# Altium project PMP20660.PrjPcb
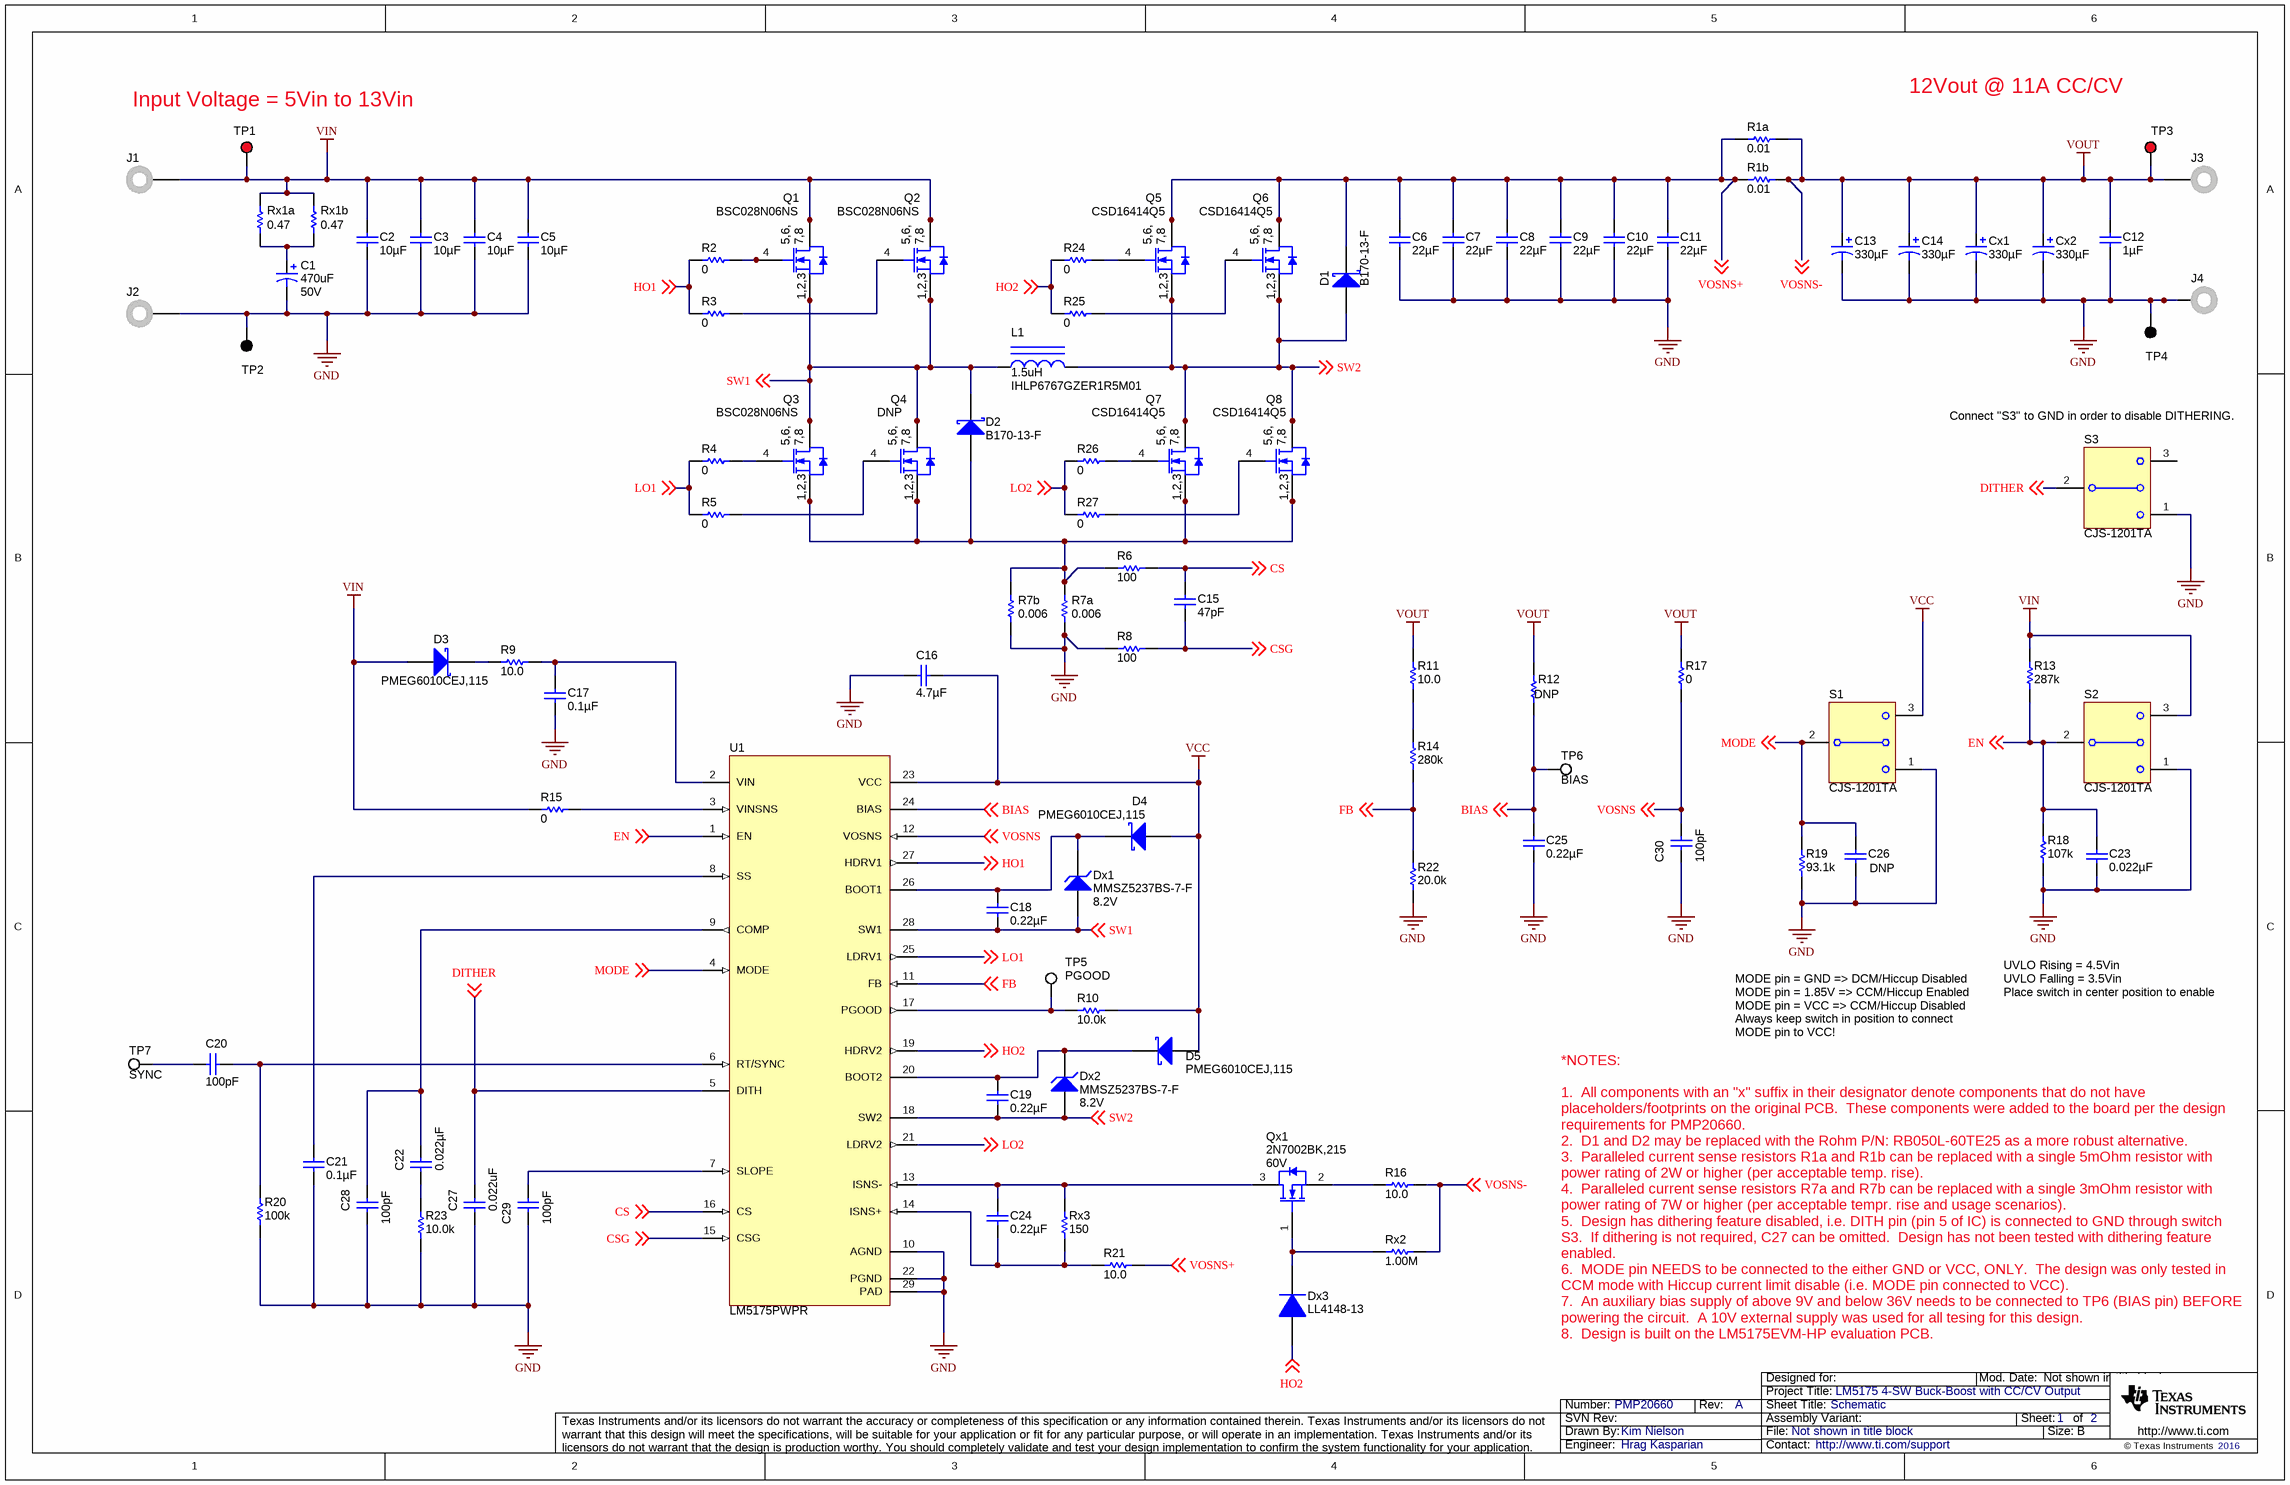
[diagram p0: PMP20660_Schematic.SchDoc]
CopyrightYear: 2016; PRJ_Engineer: Hrag Kasparian; PRJ_Number: PMP20660; PRJ_Title: LM5175 4-SW Buck-Boost with CC/CV Output; SCH_Rev: A; TechSupport: http://www.ti.com/support; TID: PMP20660
2 sheets, 113 parts. Net scope: global (net labels, ports and power ports of the same name join across sheets).
Board file: PMP20660_PCB.PcbDoc
Sheets:
  PMP20660_Schematic.SchDoc
  PMP20660_Hardware.SchDoc

## Sheet PMP20660_Schematic.SchDoc: Schematic
size 431 x 279 mm; Date: Not shown in title block; ApprovedBy: Not shown in title block; CheckedBy: Not shown in title block; Author: Not shown in title block; CompanyName: Not shown in title block; DrawnBy: Kim Nielson; Engineer: Neil Gutierrez; Organization: Not shown in title block; Address1: Not shown in title block; Address2: Not shown in title block; Address3: Not shown in title block; Address4: Not shown in title block; DocumentNumber: 1; Revision: Use project parameter SCH_Rev; SheetNumber: 1; SheetTotal: 2; PageSetup: Record=PageOptions¦CenterHorizontal=True¦CenterVertical=True¦PrintScale=0.62¦XCorrection=1.00¦YCorrection=1.00¦PrintKind=0¦BorderSize=5000000¦LeftOffset=0¦BottomOffset=0¦Orientation=2¦PaperLength=1000¦PaperWidth=1000¦Scale=100¦PaperSource=15¦PrintQuality=600¦MediaType=1¦DitherType=10¦PaperKind=Letter¦PrintScaleMode=1

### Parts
C1  value 470uF  Value1: 50V  [TBD]  (hidden comment: EMVH500ADA471MMH0S)
C2  ValueDisplayed: 10µF  [1210]  (hidden comment: GRM32ER71H106KA12L)
C3  ValueDisplayed: 10µF  [1210]  (hidden comment: GRM32ER71H106KA12L)
C4  ValueDisplayed: 10µF  [1210]  (hidden comment: GRM32ER71H106KA12L)
C5  ValueDisplayed: 10µF  [1210]  (hidden comment: GRM32ER71H106KA12L)
C6  ValueDisplayed: 22µF  [1210]  (hidden comment: GRM32ER71C226ME18L)
C7  ValueDisplayed: 22µF  [1210]  (hidden comment: GRM32ER71C226ME18L)
C8  ValueDisplayed: 22µF  [1210]  (hidden comment: GRM32ER71C226ME18L)
C9  ValueDisplayed: 22µF  [1210]  (hidden comment: GRM32ER71C226ME18L)
C10  ValueDisplayed: 22µF  [1210]  (hidden comment: GRM32ER71C226ME18L)
C11  ValueDisplayed: 22µF  [1210]  (hidden comment: GRM32ER71C226ME18L)
C12  ValueDisplayed: 1µF  [0805_HV]  (hidden comment: GRM219R71E105KA88D)
C13  ValueDisplayed: 330µF  [SM_RADIAL_10AMM]  (hidden comment: 16SVP330M)
C14  ValueDisplayed: 330µF  [SM_RADIAL_10AMM]  (hidden comment: 16SVP330M)
C15  ValueDisplayed: 47pF  [0603L]  (hidden comment: GRM1885C1H470JA01D)
C16  ValueDisplayed: 4.7µF  [0805_HV]  (hidden comment: GRM21BR71C475KA73L)
C17  ValueDisplayed: 0.1µF  [0603L]  (hidden comment: GRM188R72A104KA35D)
C18  ValueDisplayed: 0.22µF  [0603L]  (hidden comment: GRM188R71E224KA88D)
C19  ValueDisplayed: 0.22µF  [0603L]  (hidden comment: GRM188R71E224KA88D)
C20  ValueDisplayed: 100pF  [0603L]  (hidden comment: GRM1885C2A101JA01D)
C21  ValueDisplayed: 0.1µF  [0603L]  (hidden comment: GRM188R72A104KA35D)
C22  ValueDisplayed: 0.022µF  [0603L]  (hidden comment: C0603C223K5RACTU)
C23  ValueDisplayed: 0.022µF  [0603]  (hidden comment: GRM188R71H223KA01D)
C24  ValueDisplayed: 0.22µF  [0603]  (hidden comment: GRM188R71E224KA88D)
C25  ValueDisplayed: 0.22µF  [0603]  (hidden comment: GRM188R71E224KA88D)
C26  DNP  [0603L]
C27  0.022uF  [0603L]
C28  ValueDisplayed: 100pF  [0603L]  (hidden comment: GRM1885C2A101JA01D)
C29  ValueDisplayed: 100pF  [0603L]  (hidden comment: GRM1885C2A101JA01D)
C30  ValueDisplayed: 100pF  [0603L]  (hidden comment: GRM1885C2A101JA01D)
Cx1  ValueDisplayed: 330µF  [SM_RADIAL_10AMM]  (hidden comment: 16SVP330M)
Cx2  ValueDisplayed: 330µF  [SM_RADIAL_10AMM]  (hidden comment: 16SVP330M)
D1  B170-13-F  [SMA]
D2  B170-13-F  [SMA]
D3  PMEG6010CEJ,115  [SOD-323F]
D4  PMEG6010CEJ,115  [SOD-323F]
D5  PMEG6010CEJ,115  [SOD-323F]
Dx1  MMSZ5237BS-7-F  value 8.2V  [SOD-323]
Dx2  MMSZ5237BS-7-F  value 8.2V  [SOD-323]
Dx3  LL4148-13  [TBD]
J1  108-0740-001  [Johnson_108-0740-001]  (value not drawn)
J2  108-0740-001  [Johnson_108-0740-001]  (value not drawn)
J3  108-0740-001  [Johnson_108-0740-001]  (value not drawn)
J4  108-0740-001  [Johnson_108-0740-001]  (value not drawn)
L1  IHLP6767GZER1R5M01  value 1.5uH
Q1  BSC028N06NS  [PG-TDSON-8]
Q2  BSC028N06NS  [PG-TDSON-8]
Q3  BSC028N06NS  [PG-TDSON-8]
Q4  DNP  [PG-TDSON-8]
Q5  CSD16414Q5  [DQH0008A]
Q6  CSD16414Q5  [DQH0008A]
Q7  CSD16414Q5  [DQH0008A]
Q8  CSD16414Q5  [DQH0008A]
Qx1  2N7002BK,215  value 60V  [SOT-23]
R1a  ValueDisplayed: 0.01  [3008M]  (hidden comment: RL7520WT-R010-F)
R1b  ValueDisplayed: 0.01  [3008M]  (hidden comment: RL7520WT-R010-F)
R2  value 0  [0603L]  (hidden comment: RC0603JR-070RL)
R3  value 0  [0603L]  (hidden comment: RC0603JR-070RL)
R4  value 0  [0603L]  (hidden comment: RC0603JR-070RL)
R5  value 0  [0603L]  (hidden comment: RC0603JR-070RL)
R6  value 100  [0603_HV]  (hidden comment: RC0603FR-07100RL)
R7a  value 0.006  [TBD]  (hidden comment: WSHM28186L000FEA)
R7b  value 0.006  [TBD]  (hidden comment: WSHM28186L000FEA)
R8  value 100  [0603_HV]  (hidden comment: RC0603FR-07100RL)
R9  value 10.0  [0603L]  (hidden comment: RC0603FR-0710RL)
R10  value 10.0k  [0603L]  (hidden comment: RC0603FR-0710KL)
R11  value 10.0  [0603L]  (hidden comment: RC0603FR-0710RL)
R12  DNP  [0603L]
R13  ValueDisplayed: 287k  [0603]  (hidden comment: CRCW0603287KFKEA)
R14  value 280k  [0603L]  (hidden comment: RC0603FR-07280KL)
R15  value 0  [0603L]  (hidden comment: RC0603JR-070RL)
R16  ValueDisplayed: 10.0  [0603]  (hidden comment: CRCW060310R0FKEA)
R17  value 0  [0603L]  (hidden comment: RC0603JR-070RL)
R18  ValueDisplayed: 107k  [0603]  (hidden comment: CRCW0603107KFKEA)
R19  ValueDisplayed: 93.1k  [0603L]  (hidden comment: RC0603FR-0793K1L)
R20  ValueDisplayed: 100k  [0603L]  (hidden comment: RC0603FR-07100KL)
R21  ValueDisplayed: 10.0  [0603]  (hidden comment: CRCW060310R0FKEA)
R22  value 20.0k  [0603L]  (hidden comment: RC0603FR-0720KL)
R23  value 10.0k  [0603L]  (hidden comment: RC0603FR-0710KL)
R24  value 0  [0603L]  (hidden comment: RC0603JR-070RL)
R25  value 0  [0603L]  (hidden comment: RC0603JR-070RL)
R26  value 0  [0603L]  (hidden comment: RC0603JR-070RL)
R27  value 0  [0603L]  (hidden comment: RC0603JR-070RL)
Rx1a  value 0.47  [TBD]  (hidden comment: RL73K3AR47J)
Rx1b  value 0.47  [TBD]  (hidden comment: RL73K3AR47J)
Rx2  ValueDisplayed: 1.00M  [0603]  (hidden comment: CRCW06031M00FKEA)
Rx3  ValueDisplayed: 150  [0603]  (hidden comment: CRCW0603150RFKEA)
S1  CJS-1201TA  [SW_CJS_1201A]
S2  CJS-1201TA  [SW_CJS_1201A]
S3  CJS-1201TA  [SW_CJS_1201A]
TP1  5005  [Keystone5005]  (value not drawn)
TP2  5006  [Keystone5006]  (value not drawn)
TP3  5005  [Keystone5005]  (value not drawn)
TP4  5006  [Keystone5006]  (value not drawn)
TP5  value PGOOD  [Keystone5007]  (hidden comment: 5007)
TP6  BIAS  [Keystone5007]
TP7  SYNC  [Keystone5007]
U1  LM5175PWPR  [PWP0028F_N]

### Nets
GND: C1.2(-) C2.2 C3.2 C4.2 C5.2 C6.2 C7.2 C8.2 C9.2 C10.2 C11.2 C12.2 C13.2(-) C14.2(-) C16.1 C17.2 C21.2 C23.2 C25.2 C26.2 C27.2 C28.2 C29.2 C30.2 Cx1.2(-) Cx2.2(-) J2.1 J4.1 R7a.1 R7b.1 R8.2 R18.1 R19.1 R20.1 R22.1 R23.1 S1.1 S2.1 S3.1 TP2.1 TP4.1 U1.10(AGND) U1.22(PGND) U1.29(PAD)
VCC: C16.2 D4.2(A) D5.2(A) R10.2 S1.3 U1.23(VCC)
VIN: C2.1 C3.1 C4.1 C5.1 D3.2(A) J1.1 Q1.5(D) Q1.6(D) Q1.7(D) Q1.8(D) Q1.9(D) Q2.5(D) Q2.6(D) Q2.7(D) Q2.8(D) Q2.9(D) R13.2 R15.2 Rx1a.2 Rx1b.2 S2.3 TP1.1
VOUT: C12.1 C13.1(+) C14.1(+) Cx1.1(+) Cx2.1(+) J3.1 R1a.2 R1b.2 R11.1 R12.1 R16.2 R17.1 Rx2.2 TP3.1 ; off-sheet VOSNS-  [also labelled VOSNS-]
BIAS: C25.1 R12.2 TP6.1 U1.24(BIAS) ; off-sheet BIAS
CS: C15.1 R6.1 U1.16(CS) ; off-sheet CS
CSG: C15.2 R8.1 U1.15(CSG) ; off-sheet CSG
DITHER: C27.1 S3.2(COM) U1.5(DITH) ; off-sheet DITHER
EN: C23.1 R13.1 R18.2 S2.2(COM) U1.1(EN) ; off-sheet EN
FB: R14.1 R22.2 U1.11(FB) ; off-sheet FB
HO1: R2.2 R3.2 U1.27(HDRV1) ; off-sheet HO1
HO2: Dx3.2(A) R24.2 R25.2 U1.19(HDRV2) ; off-sheet HO2
LO1: R4.2 R5.2 U1.25(LDRV1) ; off-sheet LO1
LO2: R26.2 R27.2 U1.21(LDRV2) ; off-sheet LO2
MODE: C26.1 R19.2 S1.2(COM) U1.4(MODE) ; off-sheet MODE
SW1: C18.1 D2.1(K) Dx1.2(A) L1.1 Q1.1(S) Q1.2(S) Q1.3(S) Q2.1(S) Q2.2(S) Q2.3(S) Q3.5(D) Q3.6(D) Q3.7(D) Q3.8(D) Q3.9(D) Q4.5(D) Q4.6(D) Q4.7(D) Q4.8(D) Q4.9(D) U1.28(SW1) ; off-sheet SW1
SW2: C19.2 D1.2(A) Dx2.2(A) L1.2 Q5.1(S) Q5.2(S) Q5.3(S) Q6.1(S) Q6.2(S) Q6.3(S) Q7.5(D) Q7.6(D) Q7.7(D) Q7.8(D) Q7.9(D) Q8.5(D) Q8.6(D) Q8.7(D) Q8.8(D) Q8.9(D) U1.18(SW2) ; off-sheet SW2
VOSNS: C30.1 R17.2 U1.12(VOSNS) ; off-sheet VOSNS
VOSNS+: C6.1 C7.1 C8.1 C9.1 C10.1 C11.1 D1.1(K) Q5.5(D) Q5.6(D) Q5.7(D) Q5.8(D) Q5.9(D) Q6.5(D) Q6.6(D) Q6.7(D) Q6.8(D) Q6.9(D) R1a.1 R1b.1 R21.2 ; off-sheet VOSNS+
NetC1_1: C1.1(+) Rx1a.1 Rx1b.1
NetC17_1: C17.1 R9.1 U1.2(VIN)
NetC18_2: C18.2 D4.1(K) Dx1.1(K) U1.26(BOOT1)
NetC19_1: C19.1 D5.1(K) Dx2.1(K) U1.20(BOOT2)
NetC20_1: C20.1 TP7.1
NetC20_2: C20.2 R20.2 U1.6(RT/SYNC)
NetC21_1: C21.1 U1.8(SS)
NetC22_1: C22.1 C28.1 U1.9(COMP)
NetC22_2: C22.2 R23.2
NetC24_1: C24.1 Qx1.3(D) Rx3.2 U1.13(ISNS-)
NetC24_2: C24.2 R21.1 Rx3.1 U1.14(ISNS+)
NetC29_1: C29.1 U1.7(SLOPE)
NetD2_2: D2.2(A) Q3.1(S) Q3.2(S) Q3.3(S) Q4.1(S) Q4.2(S) Q4.3(S) Q7.1(S) Q7.2(S) Q7.3(S) Q8.1(S) Q8.2(S) Q8.3(S) R6.2 R7a.2 R7b.2
NetD3_1: D3.1(K) R9.2
NetDx3_1: Dx3.1(K) Qx1.1(G) Rx2.1
NetQ1_4: Q1.4(G) R2.1
NetQ2_4: Q2.4(G) R3.1
NetQ3_4: Q3.4(G) R4.1
NetQ4_4: Q4.4(G) R5.1
NetQ5_4: Q5.4(G) R24.1
NetQ6_4: Q6.4(G) R25.1
NetQ7_4: Q7.4(G) R26.1
NetQ8_4: Q8.4(G) R27.1
NetQx1_2: Qx1.2(S) R16.1
NetR10_1: R10.1 TP5.1 U1.17(PGOOD)
NetR11_2: R11.2 R14.2
NetR15_1: R15.1 U1.3(VINSNS)

Not connected (* = marked no-connect by the designer): S3 3

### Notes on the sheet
- (near TP1) Input Voltage = 5Vin to 13Vin
- 12Vout @ 11A CC/CV
- (near S3) Connect "S3" to GND in order to disable DITHERING.
- MODE pin = GND => DCM/Hiccup Disabled
  MODE pin = 1.85V => CCM/Hiccup Enabled
  MODE pin = VCC => CCM/Hiccup Disabled
  Always keep switch in position to connect MODE pin to VCC!
- UVLO Rising = 4.5Vin
  UVLO Falling = 3.5Vin
  Place switch in center position to enable UVLO function.
- *NOTES:
  1.  All components with an "x" suffix in their designator denote components that do not have placeholders/footprints on the original PCB.  These components were added to the board per the design requirements for PMP20660.
  2.  D1 and D2 may be replaced with the Rohm P/N: RB050L-60TE25 as a more robust alternative.
  3.  Paralleled current sense resistors R1a and R1b can be replaced with a single 5mOhm resistor with power rating of 2W or higher (per acceptable temp. rise).
  4.  Paralleled current sense resistors R7a and R7b can be replaced with a single 3mOhm resistor with power rating of 7W or higher (per acceptable tempr. rise and usage scenarios).
  5.  Design has dithering feature disabled, i.e. DITH pin (pin 5 of IC) is connected to GND through switch S3.  If dithering is not required, C27 can be omitted.  Design has not been tested with dithering feature enabled.
  6.  MODE pin NEEDS to be connected to the either GND or VCC, ONLY.  The design was only tested in CCM mode with Hiccup current limit disable (i.e. MODE pin connected to VCC).
  7.  An auxiliary bias supply of above 9V and below 36V needs to be connected to TP6 (BIAS pin) BEFORE powering the circuit.  A 10V external supply was used for all tesing for this design.
  8.  Design is built on the LM5175EVM-HP evaluation PCB.

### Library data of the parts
C1 = Capacitor_Polarized: CAP, Al Electrolytic, 470uF, 50V, +/-%, 0.15Ohm ESR, 125C, SMT; Manufacturer: Nippon Chemi-Con; Polarized: Y; U/M: EA
C2-C5 = GRM32ER71H106KA12L: CAP, CERM, 10 µF, 50 V, +/- 10%, X7R, 1210; Manufacturer: MuRata; CompType: Capacitor; Value: 10uF; U/M: EA; Tolerance_%: 10; VDC_V: 50; Polarized: N; Cap_F: 0.00001; Value1: Unknown; Value2: 50V; TaMin_C: -55; TaMax_C: 125
C6-C11 = GRM32ER71C226ME18L: CAP, CERM, 22 µF, 16 V, +/- 20%, X7R, 1210; Manufacturer: MuRata; CompType: Capacitor; Value: 22uF; U/M: EA; Tolerance_%: 20; VDC_V: 16; Polarized: N; Cap_F: 0.000022; ESR_ohm: 0.003; Value1: 0.003 ohm; Value2: 16V; IRMS_A: 3.2; TaMin_C: -55; TaMax_C: 125
C12 = GRM219R71E105KA88D: CAP, CERM, 1 µF, 25 V, +/- 10%, X7R, 0805; Manufacturer: MuRata; Polarized: N; CompType: Capacitor; Value: 1uF; U/M: EA; Cap_F: 0.000001; Tolerance_%: 10; Value1: Unknown; VDC_V: 25; Value2: 25V; TaMin_C: -55; TaMax_C: 125; Cap_Case: 0805
C13 C14 Cx1 Cx2 = 16SVP330M: CAP, OS-CON, 330 µF, 16 V, +/- 20%, 0.016 ohm, 10x10.3 SMD; Manufacturer: Sanyo; CompType: Capacitor; Value: 330uF; U/M: EA; Tolerance_%: 20; VDC_V: 16; ESR_ohm: 0.016; Polarized: Y; Cap_F: 0.00033; Value2: 16V; IRMS_A: 4.72; TaMin_C: -55; TaMax_C: 105; Cap_Case: 10.3x10.3x12.6
C15 C26 = GRM1885C1H470JA01D: CAP, CERM, 47pF, 50V, +/-5%, C0G/NP0, 0603; Manufacturer: MuRata; Polarized: N; CompType: Capacitor; U/M: EA; Cap_F: 0.000000000047; Tolerance_%: 5; Value1: Unknown; VDC_V: 50; TaMin_C: -55; TaMax_C: 125; Cap_Case: 0603
C16 = GRM21BR71C475KA73L: CAP, CERM, 4.7 µF, 16 V, +/- 10%, X7R, 0805; Manufacturer: MuRata; Polarized: N; CompType: Capacitor; Value: 4.7uF; U/M: EA; Cap_F: 0.0000047; Tolerance_%: 10; ESR_ohm: 0.006; Value1: 0.006 ohm; VDC_V: 16; Value2: 16V; TaMin_C: -55; TaMax_C: 125; Cap_Case: 0805
C17 C21 = GRM188R72A104KA35D: CAP, CERM, 0.1uF, 100V, +/-10%, X7R, 0603; Manufacturer: MuRata; Polarized: N; CompType: Capacitor; U/M: EA; Cap_F: 0.0000001; Tolerance_%: 10; Value1: Unknown; VDC_V: 100; TaMin_C: -55; TaMax_C: 125; Cap_Case: 0603
C18 C19 = GRM188R71E224KA88D: CAP, CERM, 0.22 µF, 25 V, +/- 10%, X7R, 0603; Manufacturer: MuRata; Polarized: N; CompType: Capacitor; Value: 0.22uF; U/M: EA; Cap_F: 0.00000022; Tolerance_%: 10; Value1: Unknown; VDC_V: 25; Value2: 25V; TaMin_C: -55; TaMax_C: 125; Cap_Case: 0603
C20 C28-C30 = GRM1885C2A101JA01D: CAP, CERM, 100pF, 100V, +/-5%, C0G/NP0, 0603; Manufacturer: MuRata; Polarized: N; CompType: Capacitor; U/M: EA; Cap_F: 0.0000000001; Tolerance_%: 5; Value1: Unknown; VDC_V: 100; TaMin_C: -55; TaMax_C: 125; Cap_Case: 0603
C22 = C0603C223K5RACTU: CAP, CERM, 0.022uF, 50V, +/-10%, X7R, 0603; Manufacturer: Kemet; Polarized: N; CompType: Capacitor; U/M: EA; Cap_F: 0.000000022; Tolerance_%: 10; Value1: Unknown; VDC_V: 50; TaMin_C: -55; TaMax_C: 125; Cap_Case: 0603
C23 = GRM188R71H223KA01D: CAP, CERM, 0.022 µF, 50 V, +/- 10%, X7R, 0603; Manufacturer: MuRata; Polarized: N; CompType: Capacitor; Value: 0.022uF; U/M: EA; Cap_F: 0.000000022; Tolerance_%: 10; Value1: Unknown; VDC_V: 50; Value2: 50V; TaMin_C: -55; TaMax_C: 125; SizeArea_mm2: 1.28; SizeAreaWB_mm2: 4.68; SizeX_mm: 1.6; SizeY_mm: 0.8; SizeZ_mm: 1; AEC Category: Q200
C24 = GRM188R71E224KA88D: CAP, CERM, 0.22 µF, 25 V, +/- 10%, X7R, 0603; Manufacturer: MuRata; Polarized: N; CompType: Capacitor; Value: 0.22uF; U/M: EA; Cap_F: 0.00000022; Tolerance_%: 10; Value1: Unknown; VDC_V: 25; Value2: 25V; TaMin_C: -55; TaMax_C: 125; SizeArea_mm2: 1.28; SizeAreaWB_mm2: 4.68; SizeX_mm: 1.6; SizeY_mm: 0.8; SizeZ_mm: 1; AEC Category: Q200
C25 = GRM188R71E224KA88D: CAP, CERM, 0.22 µF, 25 V, +/- 10%, X7R, 0603; Manufacturer: MuRata; Polarized: N; CompType: Capacitor; Value: 0.22uF; U/M: EA; Cap_F: 0.00000022; Tolerance_%: 10; Value1: Unknown; VDC_V: 25; Value2: 25V; TaMin_C: -55; TaMax_C: 125
C27 = C0603C223K5RACTU: CAP, CERM, 0.022uF, 50V, +/-10%, X7R, 0603; Manufacturer: Kemet; Polarized: N; CompType: Capacitor; ValueDisplayed: 0.022µF; U/M: EA; Cap_F: 0.000000022; Tolerance_%: 10; Value1: Unknown; VDC_V: 50; TaMin_C: -55; TaMax_C: 125; Cap_Case: 0603
D1 D2 = B170-13-F: Diode, Schottky, 70 V, 1 A, SMA; Manufacturer: Diodes Inc.; U/M: EA; Vf_V: 0.79; Value: 70V; Value1: 1A; Value2: 0.79V; Io_A: 1; Vr_V: 70; TJmax_C: 150; RJC_CperW: 25; SizeAreaWB_mm2: 37.3428; SizeArea_mm2: 16.3228; SizeX_mm: 5.59; SizeY_mm: 2.92; SizeZ_mm: 2.87; AEC Category: Q101
D3 = PMEG6010CEJ,115: Diode, Schottky, 60 V, 1 A, SOD-323F; Manufacturer: NXP Semiconductor; U/M: EA; Vf_V: 0.66; Value: 60V; Value1: 1A; Value2: 0.66V; Io_A: 1; Vr_V: 60; TJmax_C: 150
D4 D5 = PMEG6010CEJ,115: Diode, Schottky, 60 V, 1 A, SOD-323F; Manufacturer: NXP Semiconductor; U/M: EA; Vr_V: 60; Value: 60V; Io_A: 1; Vf_V: 0.66; Value1: 1A; Value2: 0.66V; TJmax_C: 150; SizeAreaWB_mm2: 7.875; SizeArea_mm2: 3.125; SizeX_mm: 2.5; SizeY_mm: 1.25; SizeZ_mm: 0.8; AEC Category: Q101
Dx1 Dx2 = MMSZ5237BS-7-F: Diode, Zener, 8.2 V, 200 mW, SOD-323; Manufacturer: Diodes Inc.; SymbolCreator: a0412235; U/M: EA; Power_W: 0.2; Vz_V: 8.2; Value1: 0.2W; RJA_CperW: 350; SizeAreaWB_mm2: 8.695; SizeArea_mm2: 3.645; SizeX_mm: 2.7; SizeY_mm: 1.35; SizeZ_mm: 1; AEC Category: Q101
Dx3 = Diode: Diode, Standard, 75V, 150mA, MINI-MELF; Manufacturer: Diodes Inc.; U/M: EA
J1-J4 = 108-0740-001: Standard Banana Jack, Uninsulated, 15A; Manufacturer: Emerson Network Power; SymbolCreator: a0412235; CompType: Connector; U/M: EA
L1 = Inductor_Iron: Inductor, Molded, Shielded, 1.5uH, 42Arms, 65Asat, 1.88mOhm, SMT; Manufacturer: Vishay Dale; U/M: EA
Q1-Q4 = BSC028N06NS: MOSFET, N-CH, 60 V, 100 A, PG-TDSON-8; Manufacturer: Infineon Technologies; Alternate Manufacturer: None; U/M: EA; ChType: N; Value: 60V; VdsMax_V: 60; Value1: ? ohm; Value2: 37 nC; QgTyp_nC: 37; Vgs_V: 20; IdsMax_A: 100
Q5-Q8 = CSD16414Q5: MOSFET, N-CH, 25 V, 100 A, VSON-CLIP-8; Manufacturer: Texas Instruments; Alternate Manufacturer: None; U/M: EA; ChType: N; Value: 25V; VdsMax_V: 25; Value1: 0.0026 ohm; Rdson45_ohm: 0.0026; Value2: 16.6 nC; QgTyp_nC: 16.6; Vgs_V: 16; IdsMax_A: 100; SizeAreaWB_mm2: 56; SizeArea_mm2: 30; SizeX_mm: 6; SizeY_mm: 5; SizeZ_mm: 1.05; AEC Category: Q101
Qx1 = MOSFET_N_D3G1S2: MOSFET, N-CH, 60V, 350mA, 1.6 Ohm @ 10Vgs, SOT-23; Manufacturer: NXP USA; U/M: EA
R1a R1b = RL7520WT-R010-F: RES, 0.01, 1%, 2 W, 3008; Manufacturer: Susumu Co Ltd; CompType: Resistor; Value: 0.01; Value_Code: R010; Tolerance_%: 1; Power_W: 2; Value2: 2W; TempCo: 350 ppm/C; SizeArea_mm2: 15; SizeAreaWB_mm2: 38; SizeX_mm: 7.5; SizeZ_mm: 0.6; EIA_Code: E96; U/M: EA; AEC Category: Q200
R2-R5 R15 R17 R24-R27 = RC0603JR-070RL: RES, 0 ohm, 5%, 0.1W, 0603; Manufacturer: Yageo America; CompType: Resistor; Value_Code: 0000; Tolerance_%: 5; Power_W: 0.1; VDC_V: 50; TempCo: 200 ppm/C; EIA_Code: E24; U/M: EA
R6 R8 = RC0603FR-07100RL: RES, 100 ohm, 1%, 0.1W, 0603; Manufacturer: Yageo America; CompType: Resistor; Value_Code: 100R; Tolerance_%: 1; Power_W: 0.1; VDC_V: 150; TempCo: 200 ppm/C; EIA_Code: E96; U/M: EA
R7a R7b = Resistor: RES, 0.006 ohm, 1%, 7W, 2818; Manufacturer: Vishay Dale; U/M: EA
R9 R11 = RC0603FR-0710RL: RES, 10.0 ohm, 1%, 0.1W, 0603; Manufacturer: Yageo America; CompType: Resistor; Res_ohm: 10; Value_Code: 10R0; Tolerance_%: 1; Power_W: 0.1; VDC_V: 150; TempCo: 200 ppm/C; EIA_Code: E96; U/M: EA
R10 R23 = RC0603FR-0710KL: RES, 10.0k ohm, 1%, 0.1W, 0603; Manufacturer: Yageo America; CompType: Resistor; Res_ohm: 10000; Value_Code: 10k0; Tolerance_%: 1; Power_W: 0.1; VDC_V: 150; TempCo: 200 ppm/C; EIA_Code: E96; U/M: EA
R12 = RC0603JR-070RL: RES, 0 ohm, 5%, 0.1W, 0603; Manufacturer: Yageo America; CompType: Resistor; Value: 0; Value_Code: 0000; Tolerance_%: 5; Power_W: 0.1; VDC_V: 50; TempCo: 200 ppm/C; EIA_Code: E24; U/M: EA
R13 = CRCW0603287KFKEA: RES, 287 k, 1%, 0.1 W, 0603; Manufacturer: Vishay-Dale; CompType: Resistor; Value: 287k; Res_ohm: 287000; Tolerance_%: 1; Power_W: 0.1; Value2: 0.1W; VDC_V: 75; TempCo: 100 ppm/C; EIA_Code: E96; U/M: EA; SizeArea_mm2: 1.28; SizeX_mm: 1.6; SizeY_mm: 0.8; AEC Category: Q200
R14 = RC0603FR-07280KL: RES, 280k ohm, 1%, 0.1W, 0603; Manufacturer: Yageo America; CompType: Resistor; Res_ohm: 280000; Tolerance_%: 1; Power_W: 0.1; VDC_V: 150; TempCo: 200 ppm/C; EIA_Code: E96; U/M: EA
R16 R21 = CRCW060310R0FKEA: RES, 10.0, 1%, 0.1 W, 0603; Manufacturer: Vishay-Dale; CompType: Resistor; Value: 10.0; Res_ohm: 10; Value_Code: 10R0; Tolerance_%: 1; Power_W: 0.1; Value2: 0.1W; VDC_V: 75; TempCo: 100 ppm/C; EIA_Code: E96; U/M: EA; SizeArea_mm2: 1.28; SizeX_mm: 1.6; SizeY_mm: 0.8; AEC Category: Q200
R18 = CRCW0603107KFKEA: RES, 107 k, 1%, 0.1 W, 0603; Manufacturer: Vishay-Dale; CompType: Resistor; Value: 107k; Res_ohm: 107000; Tolerance_%: 1; Power_W: 0.1; Value2: 0.1W; VDC_V: 75; TempCo: 100 ppm/C; EIA_Code: E96; U/M: EA; SizeArea_mm2: 1.28; SizeX_mm: 1.6; SizeY_mm: 0.8; AEC Category: Q200
R19 = RC0603FR-0793K1L: RES, 93.1 k, 1%, 0.1 W, 0603; Manufacturer: Yageo America; CompType: Resistor; Value: 93.1k; Res_ohm: 93100; Value_Code: 93k1; Tolerance_%: 1; Power_W: 0.1; Value2: 0.1W; VDC_V: 150; TempCo: 200 ppm/C; EIA_Code: E96; U/M: EA
R20 = RC0603FR-07100KL: RES, 100 k, 1%, 0.1 W, 0603; Manufacturer: Yageo America; CompType: Resistor; Value: 100k; Res_ohm: 100000; Tolerance_%: 1; Power_W: 0.1; Value2: 0.1W; VDC_V: 150; TempCo: 200 ppm/C; EIA_Code: E96; U/M: EA
R22 = RC0603FR-0720KL: RES, 20.0k ohm, 1%, 0.1W, 0603; Manufacturer: Yageo America; CompType: Resistor; Res_ohm: 20000; Value_Code: 20k0; Tolerance_%: 1; Power_W: 0.1; VDC_V: 150; TempCo: 200 ppm/C; EIA_Code: E96; U/M: EA
Rx1a Rx1b = Resistor: RES, 0.47 ohm, 5%, 1W, 2512; Manufacturer: TE; U/M: EA
Rx2 = CRCW06031M00FKEA: RES, 1.00 M, 1%, 0.1 W, 0603; Manufacturer: Vishay-Dale; CompType: Resistor; Value: 1.00Meg; Res_ohm: 1000000; Value_Code: 1M00; Tolerance_%: 1; Power_W: 0.1; Value2: 0.1W; VDC_V: 75; TempCo: 100 ppm/C; SizeArea_mm2: 1.28; SizeX_mm: 1.6; SizeY_mm: 0.8; EIA_Code: E96; U/M: EA; AEC Category: Q200
Rx3 = CRCW0603150RFKEA: RES, 150, 1%, 0.1 W, 0603; Manufacturer: Vishay-Dale; CompType: Resistor; Value: 150; Value_Code: 150R; Tolerance_%: 1; Power_W: 0.1; Value2: 0.1W; VDC_V: 75; TempCo: 100 ppm/C; SizeArea_mm2: 1.28; SizeX_mm: 1.6; SizeY_mm: 0.8; EIA_Code: E96; U/M: EA; AEC Category: Q200
S1-S3 = CJS-1201TA: Slide SW, SPDT 0.1A 50VDC; Manufacturer: Copal Electronics; SymbolCreator: a0799628; VDC_V: 50; SwitchFunction: On-Off-On; PositionCount: 1; CurrentRating_mA: 100; CompType: Switch
TP1 TP3 = 5005: Test Point, Compact, Red, TH; Manufacturer: Keystone; CompType: Test Point Loop; U/M: EA
TP2 TP4 = 5006: Test Point, Compact, Black, TH; Manufacturer: Keystone; CompType: Test Point Loop; U/M: EA
TP5-TP7 = 5007: Test Point, Compact, White, TH; Manufacturer: Keystone; CompType: Test Point Loop; U/M: EA
U1 = LM5175PWPR: 42V Wide VIN 4-Switch Synchronous Buck-Boost Controller, PWP0028F; Alternate PartNumber: LM5175PWPT; Manufacturer: Texas Instruments; SymbolCreator: a0411947; CompType: IC; U/M: EA

## Sheet PMP20660_Hardware.SchDoc: Hardware
size 431 x 279 mm; Date: Not shown in title block; ApprovedBy: Not shown in title block; CheckedBy: Not shown in title block; Author: Not shown in title block; CompanyName: Not shown in title block; DrawnBy: a0413446; Engineer: Not shown in title block; Organization: Not shown in title block; Address1: Not shown in title block; Address2: Not shown in title block; Address3: Not shown in title block; Address4: Not shown in title block; DocumentNumber: 2; Revision: Use project parameter SCH_Rev; SheetNumber: 2; SheetTotal: 2; PageSetup: Record=PageOptions¦CenterHorizontal=True¦CenterVertical=True¦PrintScale=1.00¦XCorrection=1.00¦YCorrection=1.00¦PrintKind=0¦BorderSize=5000000¦LeftOffset=0¦BottomOffset=0¦Orientation=2¦PaperLength=1000¦PaperWidth=1000¦Scale=100¦PaperSource=15¦PrintQuality=600¦MediaType=1¦DitherType=10¦PaperKind=Letter¦PrintScaleMode=1
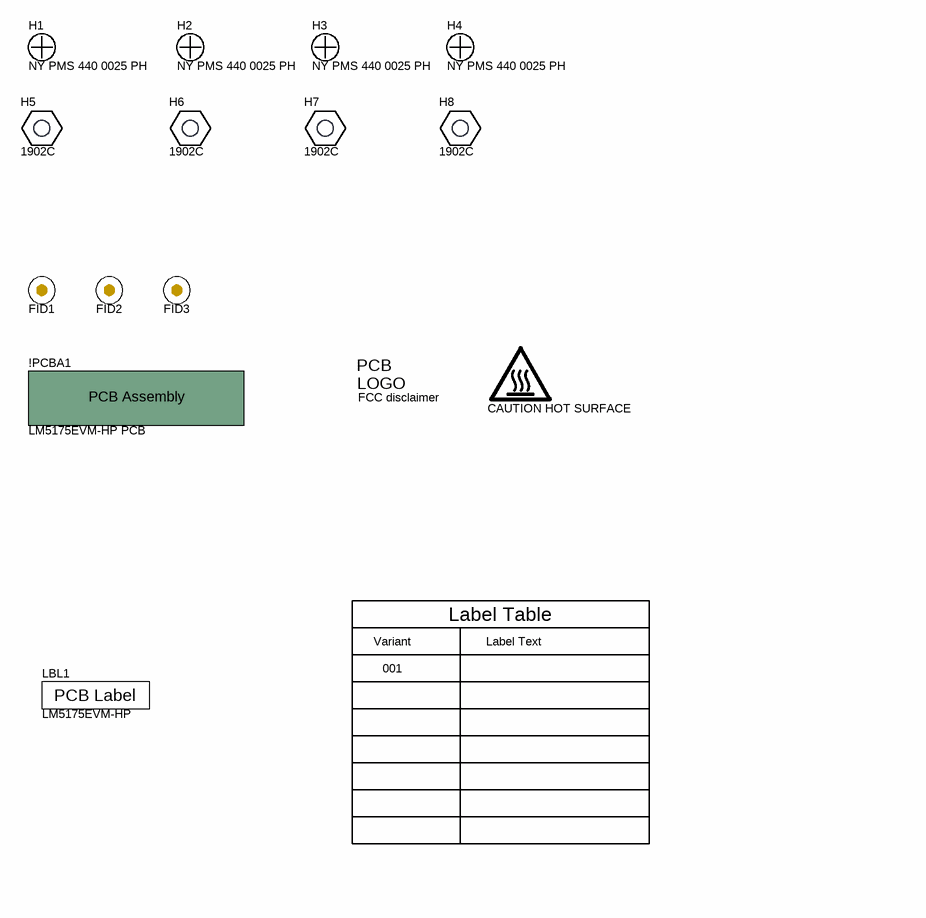
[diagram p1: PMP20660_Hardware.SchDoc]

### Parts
!PCBA1  LM5175EVM-HP PCB  (mechanical)
FID1  Fiducial  [Fiducial10-20]  (value not drawn)
FID2  Fiducial  [Fiducial10-20]  (value not drawn)
FID3  Fiducial  [Fiducial10-20]  (value not drawn)
H1  NY PMS 440 0025 PH  [NY PMS 440 0025 PH]
H2  NY PMS 440 0025 PH  [NY PMS 440 0025 PH]
H3  NY PMS 440 0025 PH  [NY PMS 440 0025 PH]
H4  NY PMS 440 0025 PH  [NY PMS 440 0025 PH]
H5  1902C  [Keystone_1902C]
H6  1902C  [Keystone_1902C]
H7  1902C  [Keystone_1902C]
H8  1902C  [Keystone_1902C]
LBL1  LM5175EVM-HP  [Label_650x200]
Logo1  FCC disclaimer  [FCC_disclaimer_stacked]  (no BOM)
LOGO2  CAUTION HOT SURFACE  [IEC_HotSurface_Small]  (no BOM)

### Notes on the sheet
- Variant
- Label Table
- Label Text
- 001

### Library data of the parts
!PCBA1 = PCBA: Manufacturer: Used in BOM report; SymbolCreator: a0412235; U/M: EA
FID1-FID3 = Fiducial: Fiducial mark.  There is nothing to buy or mount.; SymbolCreator: codlsc
H1-H4 = NY PMS 440 0025 PH: Machine Screw, Round, #4-40 x 1/4, Nylon, Philips panhead; Manufacturer: B&F Fastener Supply; CompType: Hardware; SymbolCreator: codlsc; U/M: EA
H5-H8 = 1902C: Standoff, Hex, 0.5"L #4-40 Nylon; Manufacturer: Keystone; CompType: Hardware; SymbolCreator: a0412235
LBL1 = THT-14-423-10: Thermal Transfer Printable Labels, 0.650" W x 0.200" H - 10,000 per roll; Manufacturer: Brady; SymbolCreator: a0412235; CompType: Label; Note: Size: 0.65" x 0.20 "
Logo1 = FCC_disclaimer: SymbolCreator: codlsc
LOGO2 = IEC_HotSurface: IEC 61010-1 Hot Surface Warning; SymbolCreator: a0412235

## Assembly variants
001: not fitted C26 FID1 FID2 FID3 Q4 R12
